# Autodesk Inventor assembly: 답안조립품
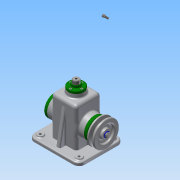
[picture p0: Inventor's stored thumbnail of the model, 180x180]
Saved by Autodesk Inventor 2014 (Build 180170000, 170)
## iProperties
Created: 2015-12
Part Number: 답안조립품
Document SubType Name: Assembly
Designer: Administrator
Author: Administrator
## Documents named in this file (19)
- D:\451225V1002\답안조립품.iam
- D:\451225V1002\1-본체.ipt
- D:\451225V1002\고정핀.ipt
- D:\451225V1002\뒤커버.ipt
- D:\451225V1002\링크.ipt
- D:\451225V1002\멈춤링 6 x 5.ipt
- D:\451225V1002\멈춤링 15 x 1.ipt
- D:\451225V1002\베어링 15 x 35 x 11.ipt
- D:\451225V1002\볼트 M3 x 8.ipt
- D:\451225V1002\볼트 M4 x 10.ipt
- D:\451225V1002\볼트 M6 x 12.ipt
- D:\451225V1002\상부부시.ipt
- D:\451225V1002\슬라이드바.ipt
- D:\451225V1002\앞커버.ipt
- D:\451225V1002\오일실 15 25 7.ipt
- D:\451225V1002\와셔.ipt
- D:\451225V1002\키 5 x 5 x 14.ipt
- D:\451225V1002\편심축.ipt
- D:\451225V1002\V-벨트풀리.ipt
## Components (9 placed, 6 different names)
1. 1-본체:1
2. 고정핀:1 — 플러쉬:2
3. ISO 4762 M4 x 10:1
4. ISO 4018 M6 x 12:1 — 각도:3
5. V-벨트풀리:1 — 각도:2
6. ISO 4762 M3 x 8:1
7. ISO 4762 M3 x 8:2
8. ISO 4762 M3 x 8:3
9. ISO 4762 M3 x 8:4
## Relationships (3: Angle 2, Flush 1)
- 각도:2 [Angle]: V-벨트풀리:1
- 각도:3 [Angle]: ISO 4018 M6 x 12:1
- 플러쉬:2 [Flush]: 고정핀:1
